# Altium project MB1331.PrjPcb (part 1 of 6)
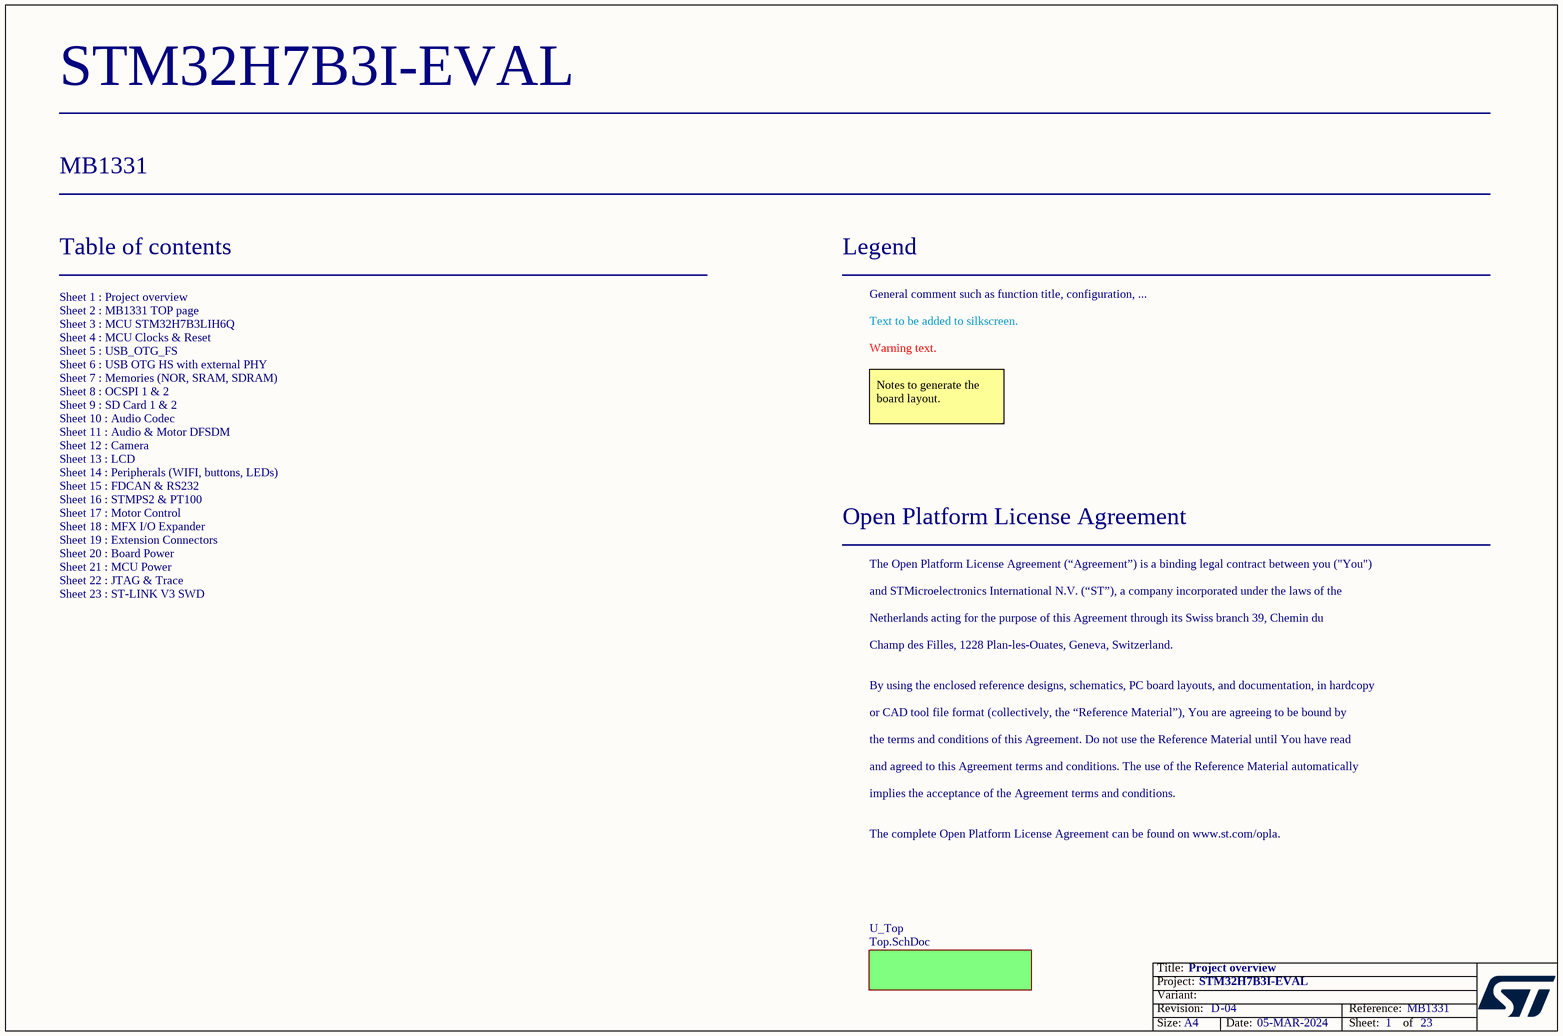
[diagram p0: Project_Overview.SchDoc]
Board_Assembly_Revision: 04; Board_Document_Date: 05-MAR-2024; Board_Name: STM32H7B3I-EVAL; Board_PCB_Revision: D; Board_Reference: MB1331
23 sheets, 916 parts. Net scope: flat (ports and power ports of the same name join across sheets).
Board file: MB1331.PcbDoc
Sheets:
  Project_Overview.SchDoc
    U_Top = Top.SchDoc
      U_SDcard = SDcard.SchDoc
      U_Camera = Camera.SchDoc
      U_MCU = MCU.SchDoc
      U_Audio_Codec = Audio_Codec.SchDoc
      U_DFSDM_Audio&Motor = DFSDM_Audio&Motor.SchDoc
      U_LCD = LCD.SchDoc
      U_JTAG&Trace = JTAG&Trace.SchDoc
      U_MCU_Clock&Reset = MCU_Clock&Reset.SchDoc
      U_Memory = Memory.SchDoc
      U_MFX = MFX.SchDoc
      U_MotorControl = MotorControl.SchDoc
      U_OCSPI = OCSPI.SchDoc
      U_Peripherals = Peripherals.SchDoc
      U_Power_Board = Power_Board.SchDoc
      U_STLink_V3E_SWD = STLink_V3E_SWD.SchDoc
      U_ExtensionConnector = ExtensionConnector.SchDoc
      U_USB_OTG_FS = USB_OTG_FS.SchDoc
      U_USB_OTG_HS_externalPHY = USB_OTG_HS_externalPHY.SchDoc
      U_FDCAN&RS232 = FDCAN&RS232.SchDoc
      U_STMPS2&PT100 = STMPS2&PT100.SchDoc
      U_Power_MCU = Power_MCU.SchDoc

## Sheet Project_Overview.SchDoc: Project overview
size A4; Date: Not used; ApprovedBy: Not used; CheckedBy: Not used; Author: Not used; CompanyName: STMicroelectronics; DrawnBy: Not used; Engineer: Not used; Organization: Not used; Address1: Not used; Address2: Not used; Address3: Not used; Address4: Not used; DocumentNumber: Not used; Revision: Not used; SheetNumber: 1; SheetTotal: 23

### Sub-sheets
U_Top = Top.SchDoc: no entries

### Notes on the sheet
- Table of contents
- Legend
- General comment such as function title, configuration, ...
- Text to be added to silkscreen.
- Warning text.
- Notes to generate the board layout.
- Open Platform License Agreement
- The Open Platform License Agreement (“Agreement”) is a binding legal contract between you ("You")
- Sheet 1 : Project overview
  Sheet 2 : MB1331 TOP page
  Sheet 3 : MCU STM32H7B3LIH6Q
  Sheet 4 : MCU Clocks & Reset
  Sheet 5 : USB_OTG_FS
  Sheet 6 : USB OTG HS with external PHY
  Sheet 7 : Memories (NOR, SRAM, SDRAM)
  Sheet 8 : OCSPI 1 & 2
  Sheet 9 : SD Card 1 & 2
  Sheet 10 : Audio Codec
  Sheet 11 : Audio & Motor DFSDM
  Sheet 12 : Camera
  Sheet 13 : LCD
  Sheet 14 : Peripherals (WIFI, buttons, LEDs)
  Sheet 15 : FDCAN & RS232
  Sheet 16 : STMPS2 & PT100
  Sheet 17 : Motor Control
  Sheet 18 : MFX I/O Expander
  Sheet 19 : Extension Connectors
  Sheet 20 : Board Power
  Sheet 21 : MCU Power
  Sheet 22 : JTAG & Trace
  Sheet 23 : ST-LINK V3 SWD
- and STMicroelectronics International N.V. (“ST”), a company incorporated under the laws of the
- Netherlands acting for the purpose of this Agreement through its Swiss branch 39, Chemin du
- Champ des Filles, 1228 Plan-les-Ouates, Geneva, Switzerland.
- By using the enclosed reference designs, schematics, PC board layouts, and documentation, in hardcopy
- or CAD tool file format (collectively, the “Reference Material”), You are agreeing to be bound by
- the terms and conditions of this Agreement. Do not use the Reference Material until You have read
- and agreed to this Agreement terms and conditions. The use of the Reference Material automatically
- implies the acceptance of the Agreement terms and conditions.
- The complete Open Platform License Agreement can be found on www.st.com/opla.

## Sheet Top.SchDoc: MB1331 TOP page
size A3; Date: Not used; ApprovedBy: Not used; CheckedBy: Not used; Author: Not used; CompanyName: STMicroelectronics; DrawnBy: Not used; Engineer: Not used; Organization: Not used; Address1: Not used; Address2: Not used; Address3: Not used; Address4: Not used; DocumentNumber: Not used; Revision: Not used; SheetNumber: 2; SheetTotal: 23
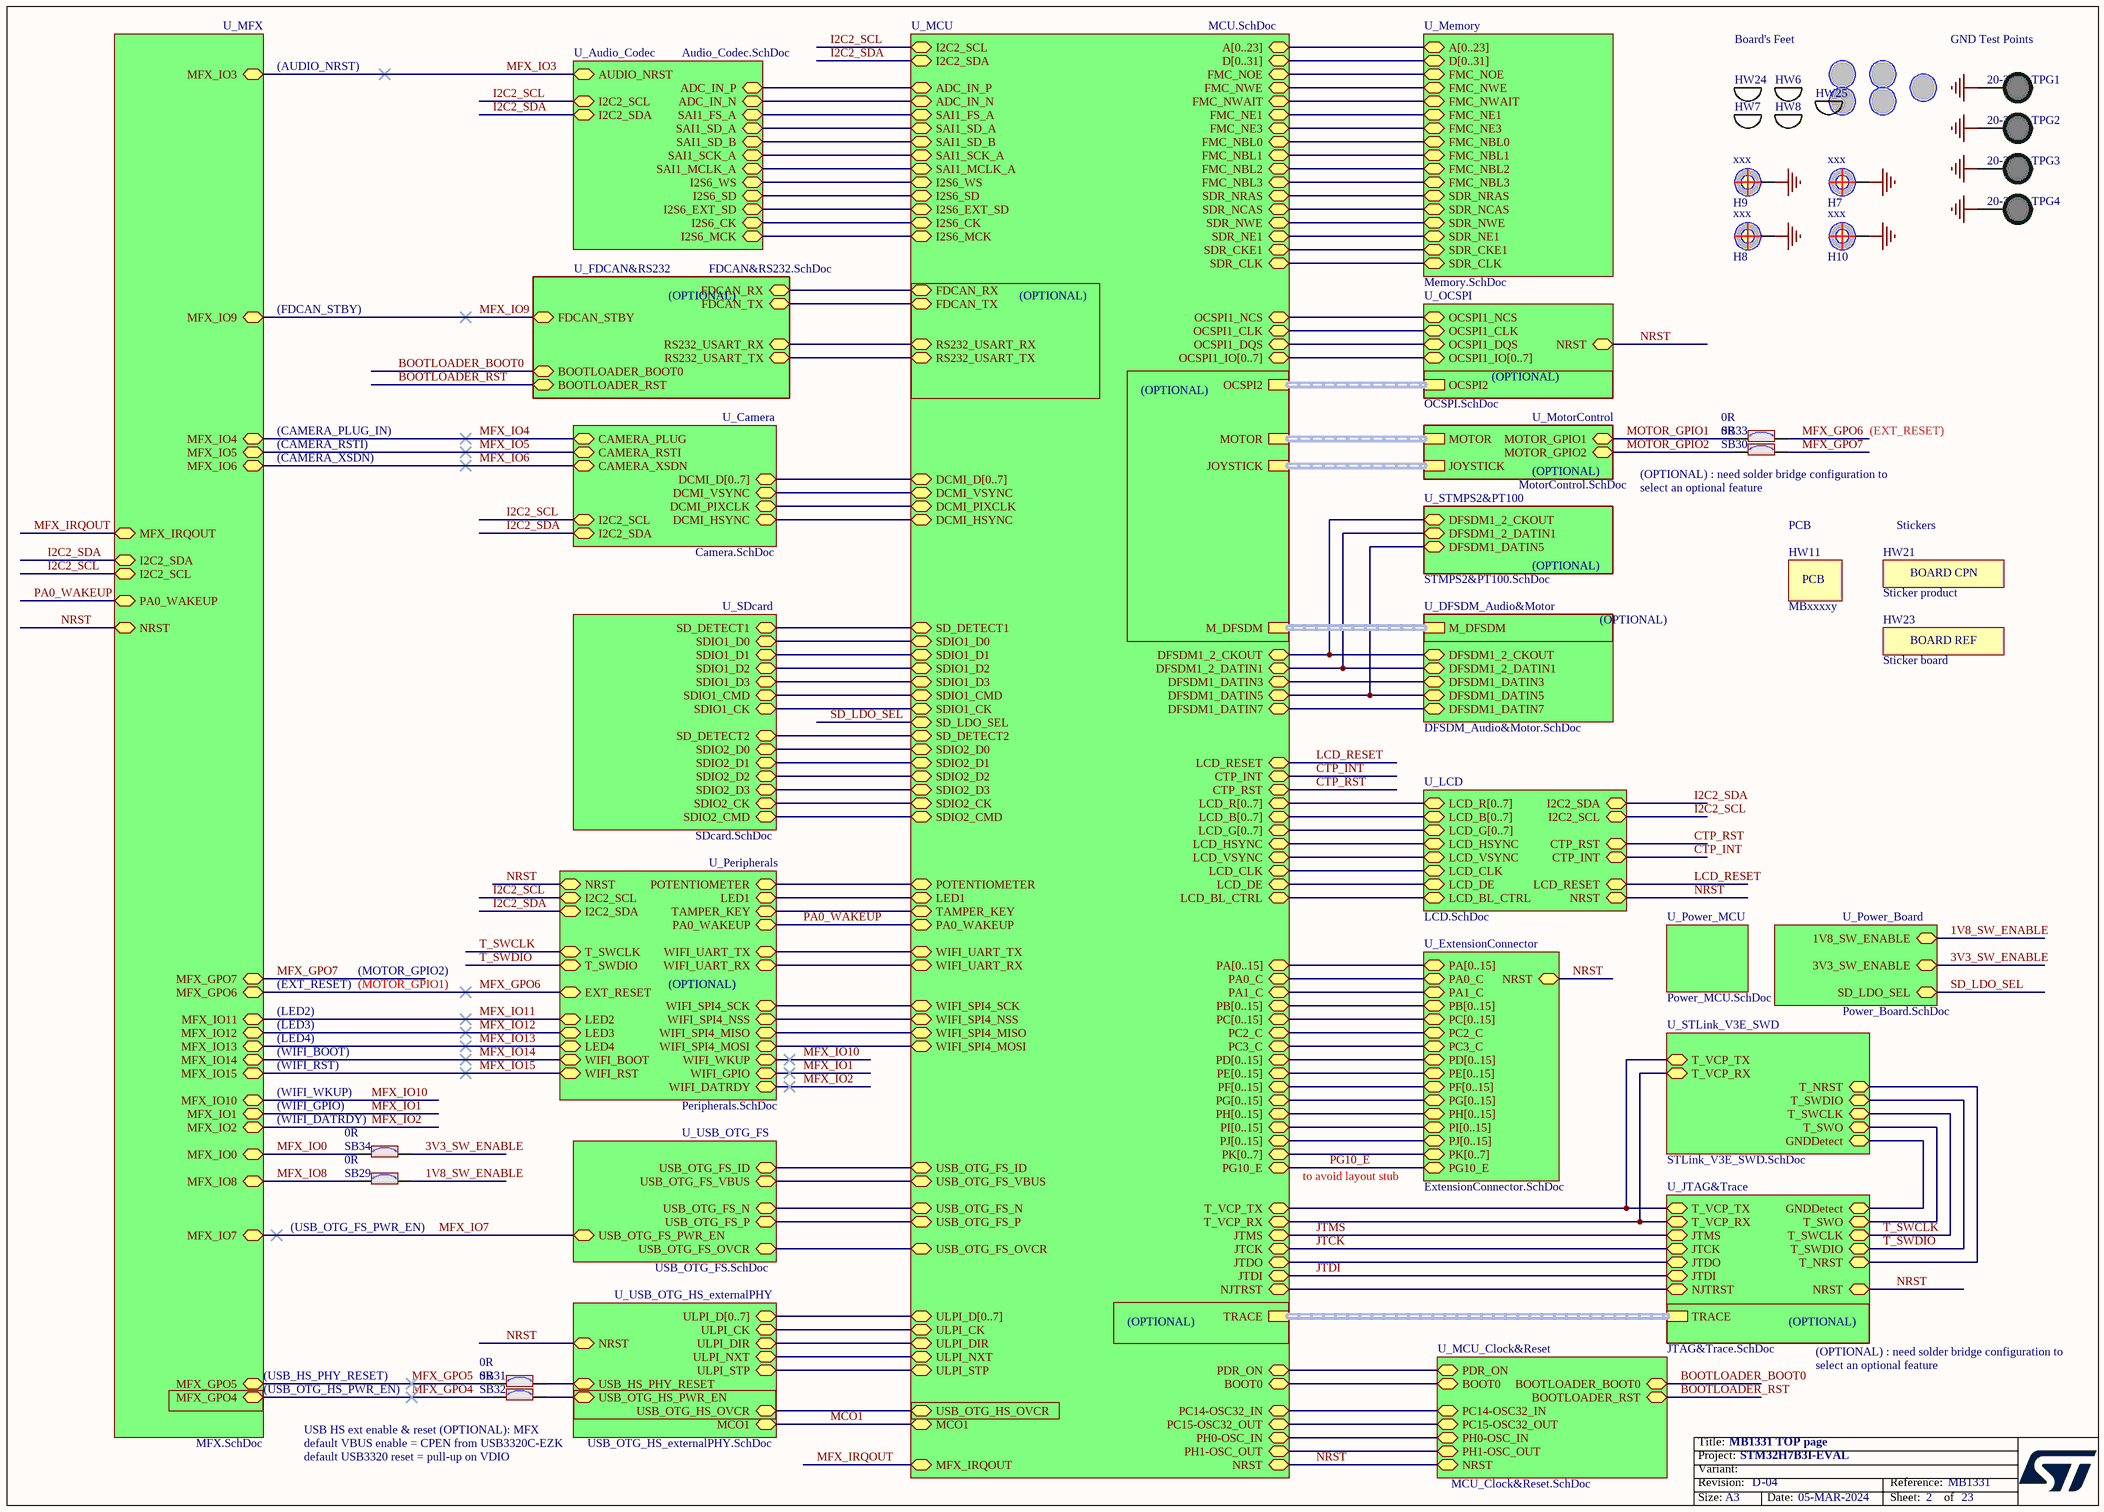
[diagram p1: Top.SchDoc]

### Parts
H7  value xxx  [PTH_M1261-3005-N_3P5X6_M3_H14]  (hidden comment: POSITION HOLE)  (no BOM)
H8  value xxx  [PTH_M1261-3005-N_3P5X6_M3_H14]  (hidden comment: POSITION HOLE)  (no BOM)
H9  value xxx  [PTH_M1261-3005-N_3P5X6_M3_H14]  (hidden comment: POSITION HOLE)  (no BOM)
H10  value xxx  [PTH_M1261-3005-N_3P5X6_M3_H14]  (hidden comment: POSITION HOLE)  (no BOM)
HW6  RUBBER_FOOT  (value not drawn)  (mechanical)
HW7  RUBBER_FOOT  (value not drawn)  (mechanical)
HW8  RUBBER_FOOT  (value not drawn)  (mechanical)
HW11  value MBxxxxy  (hidden comment: PCB)  (no BOM)
HW21  value Sticker product  [STICKER_25X9]  (hidden comment: STICKER_BOARD_CPN)  (no BOM)
HW23  value Sticker board  [STICKER_25X9]  (hidden comment: STICKER_BOARD_REF)  (no BOM)
HW24  RUBBER_FOOT  (value not drawn)  (mechanical)
HW25  RUBBER_FOOT  (value not drawn)  (mechanical)
SB29  value 0R  [SOLDER-BRIDGE_R0603-0R]  (hidden comment: SB_ON)
SB30  value 0R  [SOLDER-BRIDGE_R0603-0R]  (hidden comment: SB_ON)
SB31  value 0R  [SOLDER-BRIDGE_R0603-0R]  (hidden comment: SB_ON)
SB32  value 0R  [SOLDER-BRIDGE_R0603-0R]  (hidden comment: SB_ON)
SB33  value 0R  [SOLDER-BRIDGE_R0603-0R]  (hidden comment: SB_ON)
SB34  value 0R  [SOLDER-BRIDGE_R0603-0R]  (hidden comment: SB_ON)
TPG1  value 20-2137  [TP_PTH-1P02MM_TEST-TERMINAL_RS_101-2391_BLACK]  (hidden comment: Test_pin_conn_black)
TPG2  value 20-2137  [TP_PTH-1P02MM_TEST-TERMINAL_RS_101-2391_BLACK]  (hidden comment: Test_pin_conn_black)
TPG3  value 20-2137  [TP_PTH-1P02MM_TEST-TERMINAL_RS_101-2391_BLACK]  (hidden comment: Test_pin_conn_black)
TPG4  value 20-2137  [TP_PTH-1P02MM_TEST-TERMINAL_RS_101-2391_BLACK]  (hidden comment: Test_pin_conn_black)

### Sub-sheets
U_Audio_Codec = Audio_Codec.SchDoc: AUDIO_NRST (bidir), SAI1_SD_A (bidir), SAI1_SD_B (bidir), I2C2_SCL (bidir), I2C2_SDA (bidir), I2S6_WS (bidir), I2S6_EXT_SD (bidir), SAI1_FS_A (bidir), SAI1_SCK_A (bidir), SAI1_MCLK_A (bidir), ADC_IN_N (bidir), ADC_IN_P (bidir), I2S6_MCK (bidir), I2S6_CK (bidir), I2S6_SD (bidir)
U_Camera = Camera.SchDoc: CAMERA_RSTI (bidir), CAMERA_XSDN (bidir), DCMI_D[0..7] (bidir), CAMERA_PLUG (bidir), DCMI_HSYNC (bidir), DCMI_PIXCLK (bidir), DCMI_VSYNC (bidir), I2C2_SCL (bidir), I2C2_SDA (bidir)
U_DFSDM_Audio&Motor = DFSDM_Audio&Motor.SchDoc: DFSDM1_DATIN7 (bidir), DFSDM1_2_CKOUT (bidir), DFSDM1_2_DATIN1 (bidir), DFSDM1_DATIN3 (bidir), DFSDM1_DATIN5 (bidir), M_DFSDM (harness M_DFSDM)
U_ExtensionConnector = ExtensionConnector.SchDoc: PA[0..15] (bidir), PB[0..15] (bidir), PC[0..15] (bidir), PD[0..15] (bidir), PE[0..15] (bidir), PF[0..15] (bidir), PG[0..15] (bidir), PH[0..15] (bidir), PI[0..15] (bidir), PJ[0..15] (bidir), PK[0..7] (bidir), NRST (bidir), PA0_C (bidir), PA1_C (bidir), PC2_C (bidir), PC3_C (bidir), PG10_E (bidir)
U_FDCAN&RS232 = FDCAN&RS232.SchDoc: RS232_USART_TX (bidir), RS232_USART_RX (bidir), BOOTLOADER_BOOT0 (bidir), BOOTLOADER_RST (bidir), FDCAN_RX (bidir), FDCAN_TX (bidir), FDCAN_STBY (bidir)
U_JTAG&Trace = JTAG&Trace.SchDoc: JTMS (bidir), JTCK (bidir), JTDI (bidir), JTDO (bidir), NJTRST (bidir), NRST (bidir), TRACE (harness TRACE), T_VCP_TX (bidir), T_VCP_RX (bidir), GNDDetect (bidir), T_SWCLK (bidir), T_SWO (bidir), T_SWDIO (bidir), T_NRST (bidir)
U_LCD = LCD.SchDoc: LCD_R[0..7] (bidir), I2C2_SDA (bidir), I2C2_SCL (bidir), LCD_B[0..7] (bidir), LCD_G[0..7] (bidir), NRST (bidir), LCD_HSYNC (bidir), LCD_VSYNC (bidir), LCD_CLK (bidir), LCD_DE (bidir), CTP_INT (bidir), LCD_BL_CTRL (bidir), CTP_RST (bidir), LCD_RESET (bidir)
U_MCU = MCU.SchDoc: OCSPI1_NCS (bidir), SDR_CLK (bidir), FMC_NE3 (bidir), SDR_NCAS (bidir), SDR_NWE (bidir), SDR_NE1 (bidir), SDR_CKE1 (bidir), PH0-OSC_IN (bidir), NRST (bidir), BOOT0 (bidir), PDR_ON (bidir), FMC_NBL2 (bidir), FMC_NBL3 (bidir), LCD_HSYNC (bidir), LCD_VSYNC (bidir), LCD_CLK (bidir), PA0_WAKEUP (bidir), MCO1 (bidir), USB_OTG_FS_VBUS (bidir), USB_OTG_FS_ID (bidir), USB_OTG_FS_N (bidir), USB_OTG_FS_P (bidir), OCSPI1_CLK (bidir), T_VCP_TX (bidir), T_VCP_RX (bidir), OCSPI1_DQS (bidir), SDIO1_D0 (bidir), SDIO1_D1 (bidir), SDIO1_D2 (bidir), SDIO1_D3 (bidir), SDIO1_CK (bidir), TAMPER_KEY (bidir), PC14-OSC32_IN (bidir), PC15-OSC32_OUT (bidir), SDIO1_CMD (bidir), FMC_NOE (bidir), FMC_NWE (bidir), FMC_NWAIT (bidir), FMC_NE1 (bidir), FMC_NBL0 (bidir), FMC_NBL1 (bidir), SDR_NRAS (bidir), DFSDM1_DATIN7 (bidir), DFSDM1_2_CKOUT (bidir), DCMI_HSYNC (bidir), DCMI_PIXCLK (bidir), DCMI_VSYNC (bidir), FDCAN_RX (bidir), FDCAN_TX (bidir), PA[0..15] (bidir), PB[0..15] (bidir), PC[0..15] (bidir), PD[0..15] (bidir), PE[0..15] (bidir), PF[0..15] (bidir), PG[0..15] (bidir), PH[0..15] (bidir), PI[0..15] (bidir), PJ[0..15] (bidir), PK[0..7] (bidir), LCD_G[0..7] (bidir), LCD_B[0..7] (bidir), D[0..31] (bidir), A[0..23] (bidir), ULPI_D[0..7] (bidir), LCD_R[0..7] (bidir), LCD_DE (bidir), DFSDM1_2_DATIN1 (bidir), I2C2_SCL (bidir), I2C2_SDA (bidir), DCMI_D[0..7] (bidir), POTENTIOMETER (bidir), ULPI_NXT (bidir), ULPI_DIR (bidir), ULPI_STP (bidir), ULPI_CK (bidir), CTP_INT (bidir), CTP_RST (bidir), LCD_BL_CTRL (bidir), OCSPI1_IO[0..7] (bidir), PA0_C (bidir), PA1_C (bidir), PC2_C (bidir), PC3_C (bidir), JTMS (bidir), JTCK (bidir), JTDI (bidir), JTDO (bidir), NJTRST (bidir), DFSDM1_DATIN3 (bidir), DFSDM1_DATIN5 (bidir), LCD_RESET (bidir), MFX_IRQOUT (bidir), RS232_USART_TX (bidir), RS232_USART_RX (bidir), SDIO2_CK (bidir), SDIO2_D2 (bidir), SDIO2_D1 (bidir), SDIO2_D3 (bidir), SDIO2_D0 (bidir), SDIO2_CMD (bidir), JOYSTICK (harness JOYSTICK), MOTOR (harness MOTOR), OCSPI2 (harness OCSPI2), TRACE (harness TRACE), M_DFSDM (harness M_DFSDM), PH1-OSC_OUT (bidir), WIFI_SPI4_SCK (bidir), WIFI_SPI4_NSS (bidir), WIFI_SPI4_MISO (bidir), WIFI_SPI4_MOSI (bidir), USB_OTG_FS_OVCR (bidir), LED1 (bidir), ADC_IN_N (bidir), ADC_IN_P (bidir), USB_OTG_HS_OVCR (bidir), SD_DETECT1 (bidir), SD_DETECT2 (bidir), SD_LDO_SEL (bidir), SAI1_SD_A (bidir), SAI1_SD_B (bidir), I2S6_WS (bidir), I2S6_EXT_SD (bidir), SAI1_FS_A (bidir), SAI1_SCK_A (bidir), SAI1_MCLK_A (bidir), I2S6_MCK (bidir), I2S6_CK (bidir), I2S6_SD (bidir), PG10_E (bidir), WIFI_UART_TX (bidir), WIFI_UART_RX (bidir)
U_MCU_Clock&Reset = MCU_Clock&Reset.SchDoc: BOOTLOADER_BOOT0 (bidir), BOOTLOADER_RST (bidir), NRST (bidir), BOOT0 (bidir), PDR_ON (bidir), PH0-OSC_IN (bidir), PC14-OSC32_IN (bidir), PC15-OSC32_OUT (bidir), PH1-OSC_OUT (bidir)
U_Memory = Memory.SchDoc: FMC_NE1 (bidir), FMC_NWE (bidir), FMC_NOE (bidir), FMC_NWAIT (bidir), FMC_NBL0 (bidir), FMC_NBL1 (bidir), D[0..31] (bidir), A[0..23] (bidir), SDR_NCAS (bidir), SDR_NWE (bidir), SDR_NRAS (bidir), SDR_NE1 (bidir), SDR_CKE1 (bidir), SDR_CLK (bidir), FMC_NBL3 (bidir), FMC_NBL2 (bidir), FMC_NE3 (bidir)
U_MFX = MFX.SchDoc: MFX_IRQOUT (bidir), I2C2_SDA (bidir), I2C2_SCL (bidir), PA0_WAKEUP (bidir), NRST (bidir), MFX_IO9 (bidir), MFX_IO4 (bidir), MFX_IO5 (bidir), MFX_IO6 (bidir), MFX_IO8 (bidir), MFX_IO3 (bidir), MFX_IO7 (bidir), MFX_IO14 (bidir), MFX_IO15 (bidir), MFX_IO12 (bidir), MFX_IO11 (bidir), MFX_IO13 (bidir), MFX_GPO5 (bidir), MFX_GPO4 (bidir), MFX_IO0 (bidir), MFX_GPO6 (bidir), MFX_GPO7 (bidir), MFX_IO1 (bidir), MFX_IO2 (bidir), MFX_IO10 (bidir)
U_MotorControl = MotorControl.SchDoc: MOTOR (harness MOTOR), JOYSTICK (harness JOYSTICK), MOTOR_GPIO1 (bidir), MOTOR_GPIO2 (bidir)
U_OCSPI = OCSPI.SchDoc: NRST (bidir), OCSPI1_NCS (bidir), OCSPI1_DQS (bidir), OCSPI1_CLK (bidir), OCSPI1_IO[0..7] (bidir), OCSPI2 (harness OCSPI2)
U_Peripherals = Peripherals.SchDoc: POTENTIOMETER (bidir), LED1 (bidir), LED2 (bidir), LED3 (bidir), LED4 (bidir), WIFI_UART_RX (bidir), WIFI_UART_TX (bidir), WIFI_RST (bidir), EXT_RESET (bidir), TAMPER_KEY (bidir), NRST (bidir), PA0_WAKEUP (bidir), I2C2_SCL (bidir), I2C2_SDA (bidir), WIFI_BOOT (bidir), WIFI_SPI4_SCK (bidir), WIFI_SPI4_NSS (bidir), WIFI_SPI4_MISO (bidir), WIFI_SPI4_MOSI (bidir), T_SWCLK (bidir), T_SWDIO (bidir), WIFI_WKUP (bidir), WIFI_GPIO (bidir), WIFI_DATRDY (bidir)
U_Power_Board = Power_Board.SchDoc: 1V8_SW_ENABLE (bidir), 3V3_SW_ENABLE (bidir), SD_LDO_SEL (bidir)
U_Power_MCU = Power_MCU.SchDoc: no entries
U_SDcard = SDcard.SchDoc: SDIO1_D0 (bidir), SDIO1_D1 (bidir), SDIO1_D2 (bidir), SDIO1_D3 (bidir), SDIO1_CMD (bidir), SD_DETECT2 (bidir), SDIO1_CK (bidir), SDIO2_CK (bidir), SDIO2_D2 (bidir), SDIO2_D1 (bidir), SDIO2_D3 (bidir), SDIO2_D0 (bidir), SDIO2_CMD (bidir), SD_DETECT1 (bidir)
U_STLink_V3E_SWD = STLink_V3E_SWD.SchDoc: T_SWCLK (bidir), T_SWO (bidir), T_SWDIO (bidir), T_VCP_TX (bidir), T_VCP_RX (bidir), GNDDetect (bidir), T_NRST (bidir)
U_STMPS2&PT100 = STMPS2&PT100.SchDoc: DFSDM1_2_CKOUT (bidir), DFSDM1_2_DATIN1 (bidir), DFSDM1_DATIN5 (bidir)
U_USB_OTG_FS = USB_OTG_FS.SchDoc: USB_OTG_FS_VBUS (bidir), USB_OTG_FS_N (bidir), USB_OTG_FS_P (bidir), USB_OTG_FS_ID (bidir), USB_OTG_FS_PWR_EN (bidir), USB_OTG_FS_OVCR (bidir)
U_USB_OTG_HS_externalPHY = USB_OTG_HS_externalPHY.SchDoc: ULPI_D[0..7] (bidir), ULPI_CK (bidir), ULPI_DIR (bidir), ULPI_NXT (bidir), ULPI_STP (bidir), USB_HS_PHY_RESET (bidir), NRST (bidir), USB_OTG_HS_PWR_EN (bidir), USB_OTG_HS_OVCR (bidir), MCO1 (bidir)

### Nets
GND: H7.1 H8.1 H9.1 H10.1 TPG1.1 TPG2.1 TPG3.1 TPG4.1
1V8_SW_ENABLE: SB29.1 ; sheet U_Power_Board/1V8_SW_ENABLE
3V3_SW_ENABLE: SB34.1 ; sheet U_Power_Board/3V3_SW_ENABLE
BOOTLOADER_BOOT0: sheet U_MCU_Clock&Reset/BOOTLOADER_BOOT0, sheet U_FDCAN&RS232/BOOTLOADER_BOOT0
BOOTLOADER_RST: sheet U_MCU_Clock&Reset/BOOTLOADER_RST, sheet U_FDCAN&RS232/BOOTLOADER_RST
CTP_INT: sheet U_MCU/CTP_INT, sheet U_LCD/CTP_INT
CTP_RST: sheet U_MCU/CTP_RST, sheet U_LCD/CTP_RST
I2C2_SCL: sheet U_Camera/I2C2_SCL, sheet U_MCU/I2C2_SCL, sheet U_Audio_Codec/I2C2_SCL, sheet U_LCD/I2C2_SCL, sheet U_MFX/I2C2_SCL, sheet U_Peripherals/I2C2_SCL
I2C2_SDA: sheet U_Camera/I2C2_SDA, sheet U_MCU/I2C2_SDA, sheet U_Audio_Codec/I2C2_SDA, sheet U_LCD/I2C2_SDA, sheet U_MFX/I2C2_SDA, sheet U_Peripherals/I2C2_SDA
JTCK: sheet U_MCU/JTCK, sheet U_JTAG&Trace/JTCK
JTDI: sheet U_MCU/JTDI, sheet U_JTAG&Trace/JTDI
JTMS: sheet U_MCU/JTMS, sheet U_JTAG&Trace/JTMS
LCD_RESET: sheet U_MCU/LCD_RESET, sheet U_LCD/LCD_RESET
MCO1: sheet U_MCU/MCO1, sheet U_USB_OTG_HS_externalPHY/MCO1
MFX_GPO4: SB32.2 ; sheet U_MFX/MFX_GPO4
MFX_GPO5: SB31.2 ; sheet U_MFX/MFX_GPO5
MFX_GPO6: SB33.1 ; sheet U_MFX/MFX_GPO6, sheet U_Peripherals/EXT_RESET
MFX_GPO7: SB30.1 ; sheet U_MFX/MFX_GPO7
MFX_IO0: SB34.2 ; sheet U_MFX/MFX_IO0
MFX_IO1: sheet U_MFX/MFX_IO1, sheet U_Peripherals/WIFI_GPIO
MFX_IO2: sheet U_MFX/MFX_IO2, sheet U_Peripherals/WIFI_DATRDY
MFX_IO3: sheet U_Audio_Codec/AUDIO_NRST, sheet U_MFX/MFX_IO3
MFX_IO4: sheet U_Camera/CAMERA_PLUG, sheet U_MFX/MFX_IO4
MFX_IO5: sheet U_Camera/CAMERA_RSTI, sheet U_MFX/MFX_IO5
MFX_IO6: sheet U_Camera/CAMERA_XSDN, sheet U_MFX/MFX_IO6
MFX_IO7: sheet U_MFX/MFX_IO7, sheet U_USB_OTG_FS/USB_OTG_FS_PWR_EN
MFX_IO8: SB29.2 ; sheet U_MFX/MFX_IO8
MFX_IO9: sheet U_MFX/MFX_IO9, sheet U_FDCAN&RS232/FDCAN_STBY
MFX_IO10: sheet U_MFX/MFX_IO10, sheet U_Peripherals/WIFI_WKUP
MFX_IO11: sheet U_MFX/MFX_IO11, sheet U_Peripherals/LED2
MFX_IO12: sheet U_MFX/MFX_IO12, sheet U_Peripherals/LED3
MFX_IO13: sheet U_MFX/MFX_IO13, sheet U_Peripherals/LED4
MFX_IO14: sheet U_MFX/MFX_IO14, sheet U_Peripherals/WIFI_BOOT
MFX_IO15: sheet U_MFX/MFX_IO15, sheet U_Peripherals/WIFI_RST
MFX_IRQOUT: sheet U_MCU/MFX_IRQOUT, sheet U_MFX/MFX_IRQOUT
MOTOR_GPIO1: SB33.2 ; sheet U_MotorControl/MOTOR_GPIO1
MOTOR_GPIO2: SB30.2 ; sheet U_MotorControl/MOTOR_GPIO2
NRST: sheet U_MCU/NRST, sheet U_LCD/NRST, sheet U_JTAG&Trace/NRST, sheet U_MCU_Clock&Reset/NRST, sheet U_MFX/NRST, sheet U_OCSPI/NRST, sheet U_Peripherals/NRST, sheet U_ExtensionConnector/NRST, sheet U_USB_OTG_HS_externalPHY/NRST
PA0_WAKEUP: sheet U_MCU/PA0_WAKEUP, sheet U_MFX/PA0_WAKEUP, sheet U_Peripherals/PA0_WAKEUP
PG10_E: sheet U_MCU/PG10_E, sheet U_ExtensionConnector/PG10_E
SD_LDO_SEL: sheet U_MCU/SD_LDO_SEL, sheet U_Power_Board/SD_LDO_SEL
T_SWCLK: sheet U_JTAG&Trace/T_SWCLK, sheet U_Peripherals/T_SWCLK, sheet U_STLink_V3E_SWD/T_SWCLK
T_SWDIO: sheet U_JTAG&Trace/T_SWDIO, sheet U_Peripherals/T_SWDIO, sheet U_STLink_V3E_SWD/T_SWDIO
NetSB31_1: SB31.1 ; sheet U_USB_OTG_HS_externalPHY/USB_HS_PHY_RESET
NetSB32_1: SB32.1 ; sheet U_USB_OTG_HS_externalPHY/USB_OTG_HS_PWR_EN
(unnamed): sheet U_SDcard/SDIO1_D0, sheet U_MCU/SDIO1_D0
(unnamed): sheet U_SDcard/SDIO1_D1, sheet U_MCU/SDIO1_D1  [a separate net that carries the same name]
(unnamed): sheet U_SDcard/SDIO1_D2, sheet U_MCU/SDIO1_D2  [a separate net that carries the same name]
(unnamed): sheet U_SDcard/SDIO1_D3, sheet U_MCU/SDIO1_D3  [a separate net that carries the same name]
(unnamed): sheet U_SDcard/SDIO1_CMD, sheet U_MCU/SDIO1_CMD  [a separate net that carries the same name]
(unnamed): sheet U_SDcard/SD_DETECT2, sheet U_MCU/SD_DETECT2  [a separate net that carries the same name]
(unnamed): sheet U_SDcard/SDIO1_CK, sheet U_MCU/SDIO1_CK  [a separate net that carries the same name]
(unnamed): sheet U_SDcard/SDIO2_CK, sheet U_MCU/SDIO2_CK  [a separate net that carries the same name]
(unnamed): sheet U_SDcard/SDIO2_D2, sheet U_MCU/SDIO2_D2  [a separate net that carries the same name]
(unnamed): sheet U_SDcard/SDIO2_D1, sheet U_MCU/SDIO2_D1  [a separate net that carries the same name]
(unnamed): sheet U_SDcard/SDIO2_D3, sheet U_MCU/SDIO2_D3  [a separate net that carries the same name]
(unnamed): sheet U_SDcard/SDIO2_D0, sheet U_MCU/SDIO2_D0  [a separate net that carries the same name]
(unnamed): sheet U_SDcard/SDIO2_CMD, sheet U_MCU/SDIO2_CMD  [a separate net that carries the same name]
(unnamed): sheet U_SDcard/SD_DETECT1, sheet U_MCU/SD_DETECT1  [a separate net that carries the same name]
(unnamed): sheet U_Camera/DCMI_HSYNC, sheet U_MCU/DCMI_HSYNC  [a separate net that carries the same name]
(unnamed): sheet U_Camera/DCMI_PIXCLK, sheet U_MCU/DCMI_PIXCLK  [a separate net that carries the same name]
(unnamed): sheet U_Camera/DCMI_VSYNC, sheet U_MCU/DCMI_VSYNC  [a separate net that carries the same name]
(unnamed): sheet U_MCU/OCSPI1_NCS, sheet U_OCSPI/OCSPI1_NCS  [a separate net that carries the same name]
(unnamed): sheet U_MCU/SDR_CLK, sheet U_Memory/SDR_CLK  [a separate net that carries the same name]
(unnamed): sheet U_MCU/FMC_NE3, sheet U_Memory/FMC_NE3  [a separate net that carries the same name]
(unnamed): sheet U_MCU/SDR_NCAS, sheet U_Memory/SDR_NCAS  [a separate net that carries the same name]
(unnamed): sheet U_MCU/SDR_NWE, sheet U_Memory/SDR_NWE  [a separate net that carries the same name]
(unnamed): sheet U_MCU/SDR_NE1, sheet U_Memory/SDR_NE1  [a separate net that carries the same name]
(unnamed): sheet U_MCU/SDR_CKE1, sheet U_Memory/SDR_CKE1  [a separate net that carries the same name]
(unnamed): sheet U_MCU/PH0-OSC_IN, sheet U_MCU_Clock&Reset/PH0-OSC_IN  [a separate net that carries the same name]
(unnamed): sheet U_MCU/BOOT0, sheet U_MCU_Clock&Reset/BOOT0  [a separate net that carries the same name]
(unnamed): sheet U_MCU/PDR_ON, sheet U_MCU_Clock&Reset/PDR_ON  [a separate net that carries the same name]
(unnamed): sheet U_MCU/FMC_NBL2, sheet U_Memory/FMC_NBL2  [a separate net that carries the same name]
(unnamed): sheet U_MCU/FMC_NBL3, sheet U_Memory/FMC_NBL3  [a separate net that carries the same name]
(unnamed): sheet U_MCU/LCD_HSYNC, sheet U_LCD/LCD_HSYNC  [a separate net that carries the same name]
(unnamed): sheet U_MCU/LCD_VSYNC, sheet U_LCD/LCD_VSYNC  [a separate net that carries the same name]
(unnamed): sheet U_MCU/LCD_CLK, sheet U_LCD/LCD_CLK  [a separate net that carries the same name]
(unnamed): sheet U_MCU/USB_OTG_FS_VBUS, sheet U_USB_OTG_FS/USB_OTG_FS_VBUS  [a separate net that carries the same name]
(unnamed): sheet U_MCU/USB_OTG_FS_ID, sheet U_USB_OTG_FS/USB_OTG_FS_ID  [a separate net that carries the same name]
(unnamed): sheet U_MCU/USB_OTG_FS_N, sheet U_USB_OTG_FS/USB_OTG_FS_N  [a separate net that carries the same name]
(unnamed): sheet U_MCU/USB_OTG_FS_P, sheet U_USB_OTG_FS/USB_OTG_FS_P  [a separate net that carries the same name]
(unnamed): sheet U_MCU/OCSPI1_CLK, sheet U_OCSPI/OCSPI1_CLK  [a separate net that carries the same name]
(unnamed): sheet U_MCU/T_VCP_TX, sheet U_JTAG&Trace/T_VCP_TX, sheet U_STLink_V3E_SWD/T_VCP_TX  [a separate net that carries the same name]
(unnamed): sheet U_MCU/T_VCP_RX, sheet U_JTAG&Trace/T_VCP_RX, sheet U_STLink_V3E_SWD/T_VCP_RX  [a separate net that carries the same name]
(unnamed): sheet U_MCU/OCSPI1_DQS, sheet U_OCSPI/OCSPI1_DQS  [a separate net that carries the same name]
(unnamed): sheet U_MCU/TAMPER_KEY, sheet U_Peripherals/TAMPER_KEY  [a separate net that carries the same name]
(unnamed): sheet U_MCU/PC14-OSC32_IN, sheet U_MCU_Clock&Reset/PC14-OSC32_IN  [a separate net that carries the same name]
(unnamed): sheet U_MCU/PC15-OSC32_OUT, sheet U_MCU_Clock&Reset/PC15-OSC32_OUT  [a separate net that carries the same name]
(unnamed): sheet U_MCU/FMC_NOE, sheet U_Memory/FMC_NOE  [a separate net that carries the same name]
(unnamed): sheet U_MCU/FMC_NWE, sheet U_Memory/FMC_NWE  [a separate net that carries the same name]
(unnamed): sheet U_MCU/FMC_NWAIT, sheet U_Memory/FMC_NWAIT  [a separate net that carries the same name]
(unnamed): sheet U_MCU/FMC_NE1, sheet U_Memory/FMC_NE1  [a separate net that carries the same name]
(unnamed): sheet U_MCU/FMC_NBL0, sheet U_Memory/FMC_NBL0  [a separate net that carries the same name]
(unnamed): sheet U_MCU/FMC_NBL1, sheet U_Memory/FMC_NBL1  [a separate net that carries the same name]
(unnamed): sheet U_MCU/SDR_NRAS, sheet U_Memory/SDR_NRAS  [a separate net that carries the same name]
(unnamed): sheet U_MCU/DFSDM1_DATIN7, sheet U_DFSDM_Audio&Motor/DFSDM1_DATIN7  [a separate net that carries the same name]
(unnamed): sheet U_MCU/DFSDM1_2_CKOUT, sheet U_DFSDM_Audio&Motor/DFSDM1_2_CKOUT, sheet U_STMPS2&PT100/DFSDM1_2_CKOUT  [a separate net that carries the same name]
(unnamed): sheet U_MCU/FDCAN_RX, sheet U_FDCAN&RS232/FDCAN_RX  [a separate net that carries the same name]
(unnamed): sheet U_MCU/FDCAN_TX, sheet U_FDCAN&RS232/FDCAN_TX  [a separate net that carries the same name]
(unnamed): sheet U_MCU/LCD_DE, sheet U_LCD/LCD_DE  [a separate net that carries the same name]
(unnamed): sheet U_MCU/DFSDM1_2_DATIN1, sheet U_DFSDM_Audio&Motor/DFSDM1_2_DATIN1, sheet U_STMPS2&PT100/DFSDM1_2_DATIN1  [a separate net that carries the same name]
(unnamed): sheet U_MCU/POTENTIOMETER, sheet U_Peripherals/POTENTIOMETER  [a separate net that carries the same name]
(unnamed): sheet U_MCU/ULPI_NXT, sheet U_USB_OTG_HS_externalPHY/ULPI_NXT  [a separate net that carries the same name]
(unnamed): sheet U_MCU/ULPI_DIR, sheet U_USB_OTG_HS_externalPHY/ULPI_DIR  [a separate net that carries the same name]
(unnamed): sheet U_MCU/ULPI_STP, sheet U_USB_OTG_HS_externalPHY/ULPI_STP  [a separate net that carries the same name]
(unnamed): sheet U_MCU/ULPI_CK, sheet U_USB_OTG_HS_externalPHY/ULPI_CK  [a separate net that carries the same name]
(unnamed): sheet U_MCU/LCD_BL_CTRL, sheet U_LCD/LCD_BL_CTRL  [a separate net that carries the same name]
(unnamed): sheet U_MCU/PA0_C, sheet U_ExtensionConnector/PA0_C  [a separate net that carries the same name]
(unnamed): sheet U_MCU/PA1_C, sheet U_ExtensionConnector/PA1_C  [a separate net that carries the same name]
(unnamed): sheet U_MCU/PC2_C, sheet U_ExtensionConnector/PC2_C  [a separate net that carries the same name]
(unnamed): sheet U_MCU/PC3_C, sheet U_ExtensionConnector/PC3_C  [a separate net that carries the same name]
(unnamed): sheet U_MCU/JTDO, sheet U_JTAG&Trace/JTDO  [a separate net that carries the same name]
(unnamed): sheet U_MCU/NJTRST, sheet U_JTAG&Trace/NJTRST  [a separate net that carries the same name]
(unnamed): sheet U_MCU/DFSDM1_DATIN3, sheet U_DFSDM_Audio&Motor/DFSDM1_DATIN3  [a separate net that carries the same name]
(unnamed): sheet U_MCU/DFSDM1_DATIN5, sheet U_DFSDM_Audio&Motor/DFSDM1_DATIN5, sheet U_STMPS2&PT100/DFSDM1_DATIN5  [a separate net that carries the same name]
(unnamed): sheet U_MCU/RS232_USART_TX, sheet U_FDCAN&RS232/RS232_USART_TX  [a separate net that carries the same name]
(unnamed): sheet U_MCU/RS232_USART_RX, sheet U_FDCAN&RS232/RS232_USART_RX  [a separate net that carries the same name]
(unnamed): sheet U_MCU/PH1-OSC_OUT, sheet U_MCU_Clock&Reset/PH1-OSC_OUT  [a separate net that carries the same name]
(unnamed): sheet U_MCU/WIFI_SPI4_SCK, sheet U_Peripherals/WIFI_SPI4_SCK  [a separate net that carries the same name]
(unnamed): sheet U_MCU/WIFI_SPI4_NSS, sheet U_Peripherals/WIFI_SPI4_NSS  [a separate net that carries the same name]
(unnamed): sheet U_MCU/WIFI_SPI4_MISO, sheet U_Peripherals/WIFI_SPI4_MISO  [a separate net that carries the same name]
(unnamed): sheet U_MCU/WIFI_SPI4_MOSI, sheet U_Peripherals/WIFI_SPI4_MOSI  [a separate net that carries the same name]
(unnamed): sheet U_MCU/USB_OTG_FS_OVCR, sheet U_USB_OTG_FS/USB_OTG_FS_OVCR  [a separate net that carries the same name]
(unnamed): sheet U_MCU/LED1, sheet U_Peripherals/LED1  [a separate net that carries the same name]
(unnamed): sheet U_MCU/ADC_IN_N, sheet U_Audio_Codec/ADC_IN_N  [a separate net that carries the same name]
(unnamed): sheet U_MCU/ADC_IN_P, sheet U_Audio_Codec/ADC_IN_P  [a separate net that carries the same name]
(unnamed): sheet U_MCU/USB_OTG_HS_OVCR, sheet U_USB_OTG_HS_externalPHY/USB_OTG_HS_OVCR  [a separate net that carries the same name]
(unnamed): sheet U_MCU/SAI1_SD_A, sheet U_Audio_Codec/SAI1_SD_A  [a separate net that carries the same name]
(unnamed): sheet U_MCU/SAI1_SD_B, sheet U_Audio_Codec/SAI1_SD_B  [a separate net that carries the same name]
(unnamed): sheet U_MCU/I2S6_WS, sheet U_Audio_Codec/I2S6_WS  [a separate net that carries the same name]
(unnamed): sheet U_MCU/I2S6_EXT_SD, sheet U_Audio_Codec/I2S6_EXT_SD  [a separate net that carries the same name]
(unnamed): sheet U_MCU/SAI1_FS_A, sheet U_Audio_Codec/SAI1_FS_A  [a separate net that carries the same name]
(unnamed): sheet U_MCU/SAI1_SCK_A, sheet U_Audio_Codec/SAI1_SCK_A  [a separate net that carries the same name]
(unnamed): sheet U_MCU/SAI1_MCLK_A, sheet U_Audio_Codec/SAI1_MCLK_A  [a separate net that carries the same name]
(unnamed): sheet U_MCU/I2S6_MCK, sheet U_Audio_Codec/I2S6_MCK  [a separate net that carries the same name]
(unnamed): sheet U_MCU/I2S6_CK, sheet U_Audio_Codec/I2S6_CK  [a separate net that carries the same name]
(unnamed): sheet U_MCU/I2S6_SD, sheet U_Audio_Codec/I2S6_SD  [a separate net that carries the same name]
(unnamed): sheet U_MCU/WIFI_UART_TX, sheet U_Peripherals/WIFI_UART_TX  [a separate net that carries the same name]
(unnamed): sheet U_MCU/WIFI_UART_RX, sheet U_Peripherals/WIFI_UART_RX  [a separate net that carries the same name]
(unnamed): sheet U_JTAG&Trace/GNDDetect, sheet U_STLink_V3E_SWD/GNDDetect  [a separate net that carries the same name]
(unnamed): sheet U_JTAG&Trace/T_SWO, sheet U_STLink_V3E_SWD/T_SWO  [a separate net that carries the same name]
(unnamed): sheet U_JTAG&Trace/T_NRST, sheet U_STLink_V3E_SWD/T_NRST  [a separate net that carries the same name]

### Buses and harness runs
bus sheet U_Camera/DCMI_D[0..7] = sheet U_MCU/DCMI_D[0..7]
bus sheet U_ExtensionConnector/PA[0..15] = sheet U_MCU/PA[0..15]
bus sheet U_ExtensionConnector/PB[0..15] = sheet U_MCU/PB[0..15]
bus sheet U_ExtensionConnector/PC[0..15] = sheet U_MCU/PC[0..15]
bus sheet U_ExtensionConnector/PD[0..15] = sheet U_MCU/PD[0..15]
bus sheet U_ExtensionConnector/PE[0..15] = sheet U_MCU/PE[0..15]
bus sheet U_ExtensionConnector/PF[0..15] = sheet U_MCU/PF[0..15]
bus sheet U_ExtensionConnector/PG[0..15] = sheet U_MCU/PG[0..15]
bus sheet U_ExtensionConnector/PH[0..15] = sheet U_MCU/PH[0..15]
bus sheet U_ExtensionConnector/PI[0..15] = sheet U_MCU/PI[0..15]
bus sheet U_ExtensionConnector/PJ[0..15] = sheet U_MCU/PJ[0..15]
bus sheet U_ExtensionConnector/PK[0..7] = sheet U_MCU/PK[0..7]
bus sheet U_LCD/LCD_B[0..7] = sheet U_MCU/LCD_B[0..7]
bus sheet U_LCD/LCD_G[0..7] = sheet U_MCU/LCD_G[0..7]
bus sheet U_LCD/LCD_R[0..7] = sheet U_MCU/LCD_R[0..7]
bus sheet U_MCU/A[0..23] = sheet U_Memory/A[0..23]
bus sheet U_MCU/D[0..31] = sheet U_Memory/D[0..31]
bus sheet U_MCU/OCSPI1_IO[0..7] = sheet U_OCSPI/OCSPI1_IO[0..7]
bus sheet U_MCU/ULPI_D[0..7] = sheet U_USB_OTG_HS_externalPHY/ULPI_D[0..7]
harness sheet U_DFSDM_Audio&Motor/M_DFSDM = sheet U_MCU/M_DFSDM
harness sheet U_JTAG&Trace/TRACE = sheet U_MCU/TRACE
harness sheet U_MCU/JOYSTICK = sheet U_MotorControl/JOYSTICK
harness sheet U_MCU/MOTOR = sheet U_MotorControl/MOTOR
harness sheet U_MCU/OCSPI2 = sheet U_OCSPI/OCSPI2

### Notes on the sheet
- Board's Feet
- (near TPG1) GND Test Points
- (AUDIO_NRST)
- (FDCAN_STBY)
- (OPTIONAL)
- (CAMERA_PLUG_IN)
- (CAMERA_RSTI)
- (EXT_RESET)
- (CAMERA_XSDN)
- (near SB30) (OPTIONAL) : need solder bridge configuration to select an optional feature
- (near HW11) PCB
- (near HW21) Stickers
- (MOTOR_GPIO1)
- (MOTOR_GPIO2)
- (WIFI_BOOT)
- (LED2)
- (LED3)
- (LED4)
- (WIFI_RST)
- (WIFI_GPIO)
- (near SB34) (WIFI_DATRDY)
- (WIFI_WKUP)
- to avoid layout stub
- (near SB29) (USB_OTG_FS_PWR_EN)
- (USB_HS_PHY_RESET)
- (USB_OTG_HS_PWR_EN)
- (OPTIONAL) : need solder bridge configuration to select an optional feature
- default VBUS enable = CPEN from USB3320C-EZK
- default USB3320 reset = pull-up on VDIO
- USB HS ext enable & reset (OPTIONAL): MFX

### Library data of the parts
H7-H10 = MCD-00035: POSITION HOLE C6D3R5; Part_Type: Misc; Part_Preference: Recommended; Component_Country_Of_Origin: Unknown; ID: 2482; ShowFields: YES
HW6-HW8 HW24 HW25 = MCD-01240: Rubber Foot (diameter = 10mm, height = 8mm); Part_Type: Mechanical; Manufacturer: 3M; Part_Preference: Recommended; Value: SJ61A4; Provided_By: SUBCO; Component_Country_Of_Origin: Unknown; ID: 3256; ShowFields: YES
HW11 = MCD-00216: PCB, xxxx for PCB number, Y for PCB revision; Part_Type: Misc; Part_Preference: Forbidden; Provided_By: SUBCO; Component_Country_Of_Origin: Unknown; ID: 2653; ShowFields: YES
HW21 = MCD-00547: Sticker to mention board CPN code; Part_Type: Misc; Part_Preference: Recommended; Provided_By: SUBCO; Component_Country_Of_Origin: Unknown; ID: 3197; ShowFields: YES
HW23 = MCD-00235: Sticker to mention board reference + serial number; Part_Type: Misc; Part_Preference: Recommended; Provided_By: SUBCO; Component_Country_Of_Origin: Unknown; ID: 2632; ShowFields: YES
SB29-SB34 = MCD-00071: Solder Bridge ON; Part_Type: Resistor; Manufacturer_Part_Number: RC0603JR-070RL; Manufacturer: YAGEO; Manufacturer_HQ_COO: Unknown; Part_Preference: Recommended; Provided_By: SUBCO; Component_Country_Of_Origin: China; ID: 2521; Order_Code_RS: 199-5647; ShowFields: YES
TPG1-TPG4 = MCD-00713: Vero Technologies 1.02mm Black Terminal Post; Part_Type: Misc; Part_Preference: Recommended; Order_Code_RS: 101-2391; Provided_By: SUBCO; Component_Country_Of_Origin: UK; ID: 3032; ShowFields: YES

## Sheet SDcard.SchDoc: SD Card
size A4; Date: Not used; ApprovedBy: Not used; CheckedBy: Not used; Author: Not used; CompanyName: STMicroelectronics; DrawnBy: Not used; Engineer: Not used; Organization: Not used; Address1: Not used; Address2: Not used; Address3: Not used; Address4: Not used; DocumentNumber: Not used; Revision: Not used; SheetNumber: 9; SheetTotal: 23
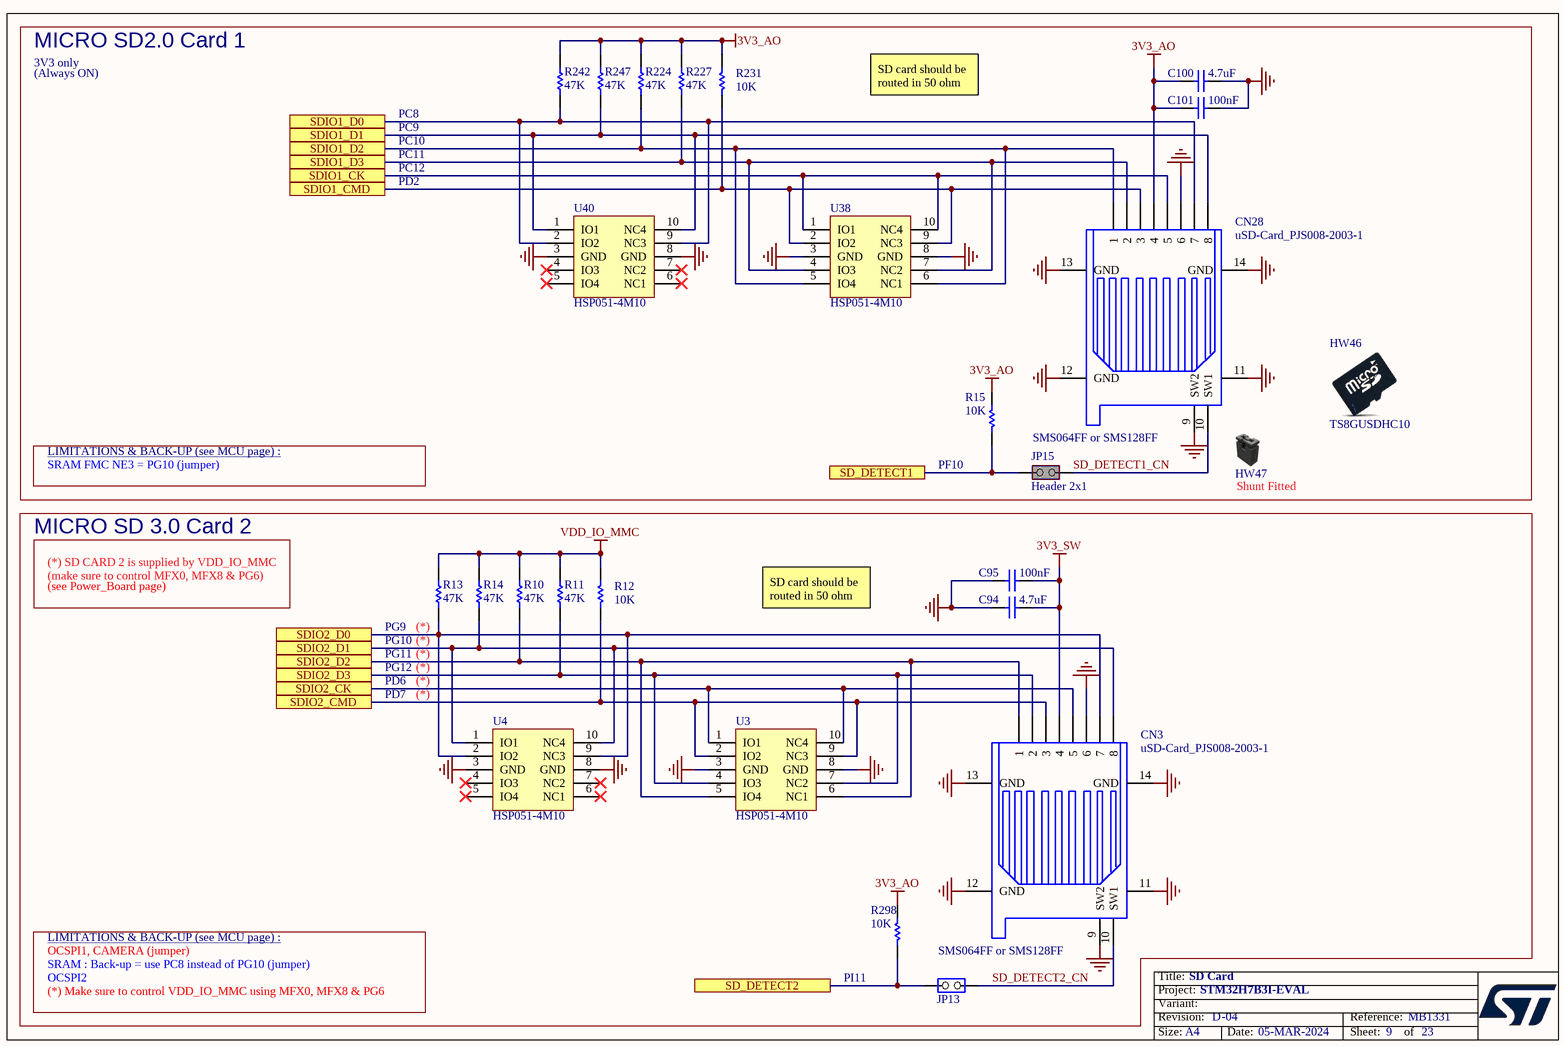
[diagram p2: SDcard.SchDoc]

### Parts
C94  value 4.7uF  [C0805]  (hidden comment: Capacitor)
C95  value 100nF  [C0402]  (hidden comment: Capacitor)
C100  value 4.7uF  [C0805]  (hidden comment: Capacitor)
C101  value 100nF  [C0402]  (hidden comment: Capacitor)
CN3  value uSD-Card_PJS008-2003-1  [CON_MICROSD_YAMAICHI_PJS008-2003-1]  (hidden comment: microSD-PJS008-2003)
CN28  value uSD-Card_PJS008-2003-1  [CON_MICROSD_YAMAICHI_PJS008-2003-1]  (hidden comment: microSD-PJS008-2003)
HW46  value TS8GUSDHC10  (hidden comment: Micro_SD_card)  (no BOM)
HW47  Shunt Black 2.54mm  (value not drawn)  (mechanical)
JP13  Jumper_Header 2x1  [CON_SAMTEC_TSW-102-07-G-S]  (value not drawn)
JP15  value Header 2x1  [CON_SAMTEC_TSW-102-07-G-S]  (hidden comment: Jumper_Header 2x1 Fitted)
R10  value 47K  [R0402]  (hidden comment: Resistor)
R11  value 47K  [R0402]  (hidden comment: Resistor)
R12  value 10K  [R0402]  (hidden comment: Resistor)
R13  value 47K  [R0402]  (hidden comment: Resistor)
R14  value 47K  [R0402]  (hidden comment: Resistor)
R15  value 10K  [R0402]  (hidden comment: Resistor)
R224  value 47K  [R0402]  (hidden comment: Resistor)
R227  value 47K  [R0402]  (hidden comment: Resistor)
R231  value 10K  [R0402]  (hidden comment: Resistor)
R242  value 47K  [R0402]  (hidden comment: Resistor)
R247  value 47K  [R0402]  (hidden comment: Resistor)
R298  value 10K  [R0402]  (hidden comment: Resistor)
U3  HSP051-4M10  [ESD_UQFN-10L_2P5X1_P050]
U4  HSP051-4M10  [ESD_UQFN-10L_2P5X1_P050]
U38  HSP051-4M10  [ESD_UQFN-10L_2P5X1_P050]
U40  HSP051-4M10  [ESD_UQFN-10L_2P5X1_P050]

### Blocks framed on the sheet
MICRO SD2.0 Card 1: C100 C101 CN28 HW46 HW47 JP15 R15 R224 R227 R231 R242 R247 U38 U40
MICRO SD 3.0 Card 2: C94 C95 CN3 JP13 R10-R14 R298 U3 U4

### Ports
SD_DETECT1, SD_DETECT2, SDIO1_CK, SDIO1_CMD, SDIO1_D0, SDIO1_D1, SDIO1_D2, SDIO1_D3, SDIO2_CK, SDIO2_CMD, SDIO2_D0, SDIO2_D1, SDIO2_D2, SDIO2_D3

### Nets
3V3_AO: C100.1 C101.1 CN28.4 R15.2 R224.2 R227.2 R231.2 R242.2 R247.2 R298.2
3V3_SW: C94.2 C95.2 CN3.4
GND: C94.1 C95.1 C100.2 C101.2 CN3.6 CN3.9(SW2) CN3.11(GND) CN3.12(GND) CN3.13(GND) CN3.14(GND) CN28.6 CN28.9(SW2) CN28.11(GND) CN28.12(GND) CN28.13(GND) CN28.14(GND) U3.3(GND) U3.8(GND) U4.3(GND) U4.8(GND) U38.3(GND) U38.8(GND) U40.3(GND) U40.8(GND)
VDD_IO_MMC: R10.2 R11.2 R12.2 R13.2 R14.2
PF10: JP15.1(COMMON) R15.1 ; port SD_DETECT1
SD_DETECT1_CN: CN28.10(SW1) JP15.2(NO)
SD_DETECT2: JP13.2(NO) R298.1 ; port SD_DETECT2
SD_DETECT2_CN: CN3.10(SW1) JP13.1(COMMON)
SDIO1_CK: CN28.5 U38.1(IO1) U38.10(NC4) ; port SDIO1_CK
SDIO1_CMD: CN28.3 R231.1 U38.2(IO2) U38.9(NC3) ; port SDIO1_CMD
SDIO1_D0: CN28.7 R242.1 U40.2(IO2) U40.9(NC3) ; port SDIO1_D0
SDIO1_D1: CN28.8 R247.1 U40.1(IO1) U40.10(NC4) ; port SDIO1_D1
SDIO1_D2: CN28.1 R224.1 U38.5(IO4) U38.6(NC1) ; port SDIO1_D2
SDIO1_D3: CN28.2 R227.1 U38.4(IO3) U38.7(NC2) ; port SDIO1_D3
SDIO2_CK: CN3.5 U3.1(IO1) U3.10(NC4) ; port SDIO2_CK
SDIO2_CMD: CN3.3 R12.1 U3.2(IO2) U3.9(NC3) ; port SDIO2_CMD
SDIO2_D0: CN3.7 R13.1 U4.2(IO2) U4.9(NC3) ; port SDIO2_D0
SDIO2_D1: CN3.8 R14.1 U4.1(IO1) U4.10(NC4) ; port SDIO2_D1
SDIO2_D2: CN3.1 R10.1 U3.5(IO4) U3.6(NC1) ; port SDIO2_D2
SDIO2_D3: CN3.2 R11.1 U3.4(IO3) U3.7(NC2) ; port SDIO2_D3

Not connected (* = marked no-connect by the designer): U4 4(IO3)* 5(IO4)* 6(NC1)* 7(NC2)*; U40 4(IO3)* 5(IO4)* 6(NC1)* 7(NC2)*

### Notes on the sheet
- 3V3 only
- (Always ON)
- PC8
- SD card should be routed in 50 ohm
- PC9
- PC10
- PC11
- PD2
- PC12
- LIMITATIONS & BACK-UP (see MCU page) :
- SMS064FF or SMS128FF
- SRAM FMC NE3 = PG10 (jumper)
- (near R15) PF10
- (near HW47) Shunt Fitted
- (see Power_Board page)
- (*) SD CARD 2 is supplied by VDD_IO_MMC
  (make sure to control MFX0, MFX8 & PG6)
- (near R13) PG9
- (near R13) PG10
- (near R13) PG11
- (near R13) (*)
- (*)
- PG12
- PD6
- PD7
- SRAM : Back-up = use PC8 instead of PG10 (jumper)
- OCSPI1, CAMERA (jumper)
- OCSPI2
- (*) Make sure to control VDD_IO_MMC using MFX0, MFX8 & PG6
- (near R298) PI11

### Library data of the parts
C94 C100 = MCD-04042: Capacitor, MLCC, 4.7uF, 16V, X7R, 10%, 0805, T=1.25mm; Manufacturer_Part_Number: 885012207053; Manufacturer: WURTH ELEKTRONIK; Part_Preference: Recommended; Order_Code_RS: 181-3521P; Component_Country_Of_Origin: Taiwan; ShowFields: YES; ID: 6158
C95 C101 = MCD-00006: Capacitor, MLCC, 100nF, 16V, X7R, 10%, 0402, T=0.5mm; Manufacturer_Part_Number: CC0402KRX7R7BB104; Manufacturer: YAGEO; Alternate_Manufacturer_Part_Number: GCM155R71C104KA55D; Alternate_Manufacturer: MURATA; Part_Preference: Recommended; Partial_Alternate_Internal_Part_Number: MCD-03299; Provided_By: SUBCO; ECCN_US: EAR99; ECCN_EU: NEC; Component_Country_Of_Origin: China; ID: 2474; Order_Code_RS: 9402047; ShowFields: YES
CN3 CN28 = MCD-00023: MicroSD Card Conn, Reversed-Type, Mnt Push-Push, Positionning holes; Part_Type: Connector; Manufacturer_Part_Number: PJS008-2003-1; Manufacturer: YAMAICHI; Part_Preference: Recommended; Provided_By: SUBCO; Component_Country_Of_Origin: Unknown; ID: 2492; ShowFields: YES
HW46 = MCD-00673: 8GB microSDHC SD card Class 10; Part_Type: Accessory; Manufacturer: TRANSCEND; Alternate_Manufacturer_Part_Number: SFSD8192N3BM1TO-I-GE-2B1-STD; Alternate_Manufacturer: SWISSBIT; Part_Preference: Recommended; Provided_By: SUBCO; Component_Country_Of_Origin: Taiwan; ID: 3072; Order_Code_RS: 758-2607; ShowFields: YES
HW47 = MCD-00043: SHUNT 2.54mm BLACK; Part_Type: Misc; Manufacturer: SAMTEC; Alternate_Manufacturer_Part_Number: 316102S111A; Alternate_Manufacturer: JIUBABA; Full_Alternate_Internal_Part_Number: MCD-02388; Manufacturer_HQ_COO: Unknown; Part_Preference: Recommended; Partial_Alternate_Internal_Part_Number: MCD-01849; Value: SNT-100-BK-G; Provided_By: SUBCO; Alternate_EMS: A; Component_Country_Of_Origin: China, Costa Rica, Malaysia, USA, Vietnam; ID: 2551; Order_Code_RS: 158-7784; ShowFields: YES
JP13 = MCD-00045: Header, 2x1, 2,54mm, VR, TH, Height 5.84mm/2.54mm; Manufacturer_Part_Number: TSW-102-07-G-S; Manufacturer: SAMTEC; Part_Type: Connector; Alternate_Manufacturer_Part_Number: 313102S111116;313102S111116; Alternate_Manufacturer: JIUBABA; LIANYI; Full_Alternate_Internal_Part_Number: MCD-02390; Part_Preference: Recommended; Partial_Alternate_Internal_Part_Number: MCD-02957, MCD-03720; Provided_By: SUBCO; Component_Country_Of_Origin: China, Costa Rica, Malaysia, USA, Vietnam; ID: 2545; Order_Code_RS: 2505044; ShowFields: YES
JP15 = MCD-00683: Header, 2x1, 2,54mm, VR, TH, Height 5.84mm/2.54mm - Shunt Fitted by default; Part_Type: Connector; Manufacturer_Part_Number: TSW-102-07-G-S; Manufacturer: SAMTEC; Alternate_Manufacturer_Part_Number: 313102S111116; Alternate_Manufacturer: LIANYI; Full_Alternate_Internal_Part_Number: MCD-02389; Part_Preference: Recommended; Partial_Alternate_Internal_Part_Number: MCD-02957, MCD-03720; Provided_By: SUBCO; Component_Country_Of_Origin: China, Costa Rica, Malaysia, USA, Vietnam; ID: 3057; Order_Code_RS: 155-5312; ShowFields: YES
R10 R11 R13 R14 R224 R227 R242 R247 = MCD-00063: Resistor,47K,0402,1%,1/16W; Manufacturer_Part_Number: RC0402FR-0747KL; Manufacturer: YAGEO; Part_Preference: Recommended; Provided_By: SUBCO; ECCN_US: EAR99; ECCN_EU: NEC; Component_Country_Of_Origin: China; ID: 2528; Order_Code_RS: 9239430; ShowFields: YES
R12 R15 R231 R298 = MCD-00053: Resistor,10K,0402,1%,1/16W; Manufacturer_Part_Number: RC0402FR-0710KL; Manufacturer: YAGEO; BMS_Part_Number: 9131590; Part_Preference: Recommended; Provided_By: SUBCO; ECCN_US: EAR99; ECCN_EU: NEC; Component_Country_Of_Origin: China; ID: 2539; Order_Code_RS: 9239359; ShowFields: YES
U3 U4 U38 U40 = MCD-00667: 4-line ESD protection for high speed lines; Manufacturer: STMICROELECTRONICS; Part_Type: Diode; BMS_Part_Number: 9179041; Manufacturer_HQ_COO: EU; Part_Preference: Recommended; Provided_By: SUBCO with ST control; ECCN_US: EAR99; ECCN_EU: NEC; Component_Country_Of_Origin: Philippines; ID: 3081; ShowFields: YES

## Sheet Camera.SchDoc: Camera
size A4; Date: Not used; ApprovedBy: Not used; CheckedBy: Not used; Author: Not used; CompanyName: STMicroelectronics; DrawnBy: Not used; Engineer: Not used; Organization: Not used; Address1: Not used; Address2: Not used; Address3: Not used; Address4: Not used; DocumentNumber: Not used; Revision: Not used; SheetNumber: 12; SheetTotal: 23
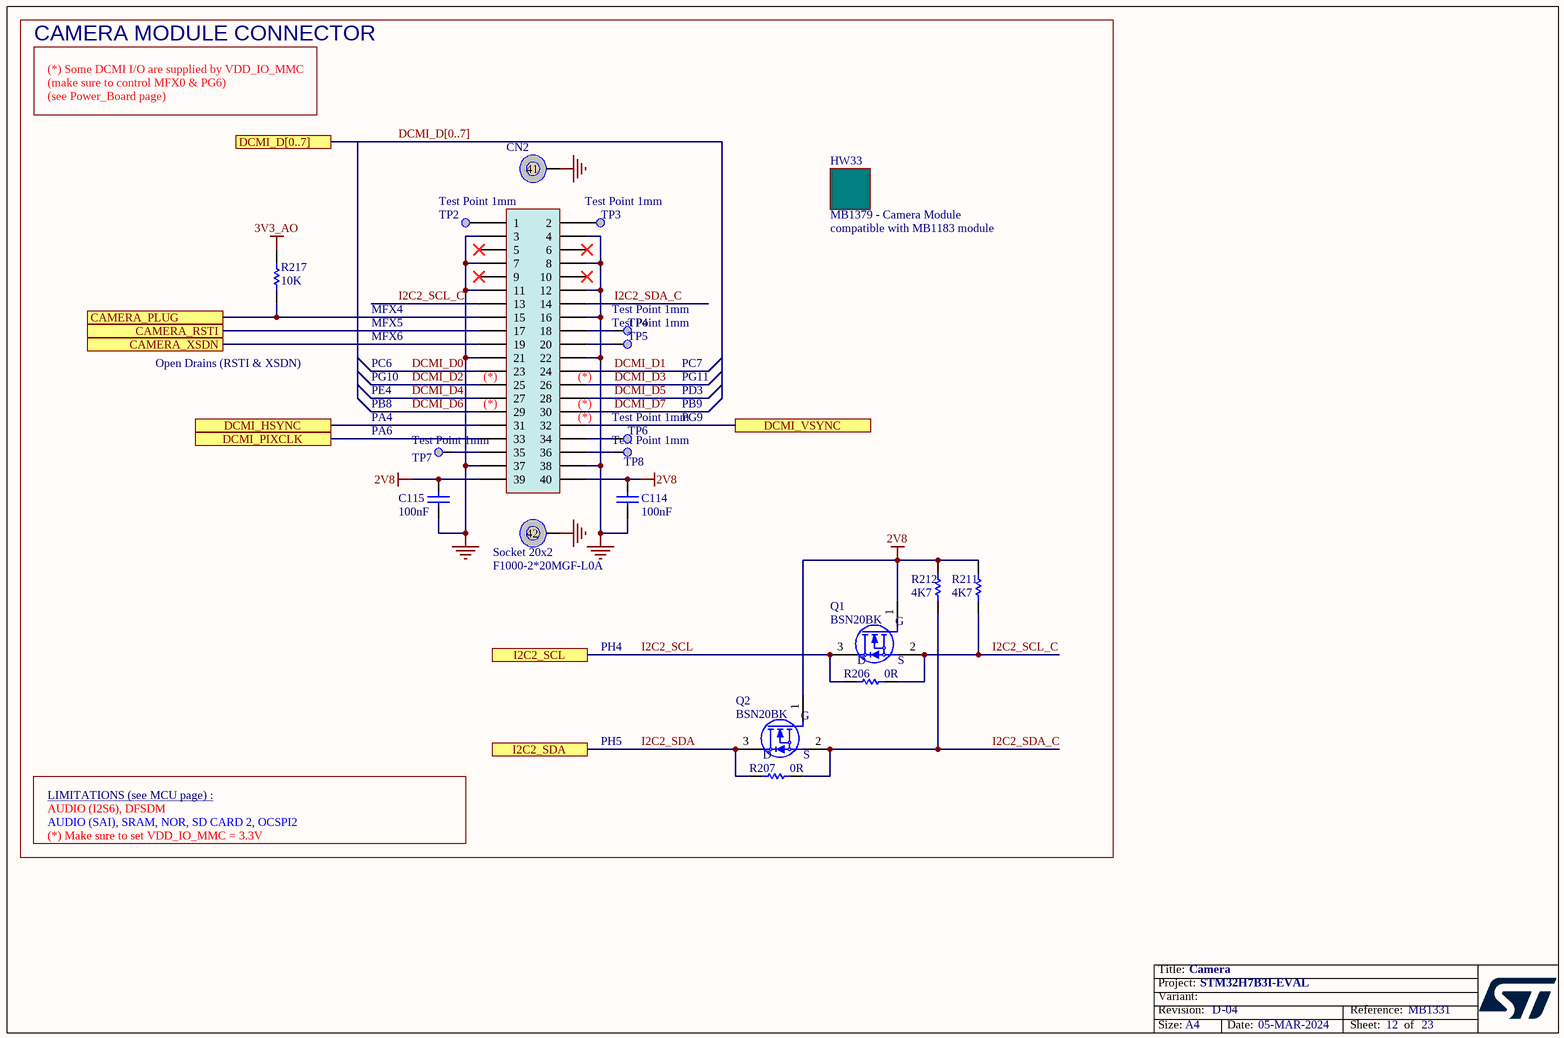
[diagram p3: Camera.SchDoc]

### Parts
C114  value 100nF  [C0402]  (hidden comment: Capacitor)
C115  value 100nF  [C0402]  (hidden comment: Capacitor)
CN2  value Socket 20x2  [CON_SAMTEC_CLM-120-02-L-D_Reverse-to-Camera]  (hidden comment: Socket 20x2 CLM_Reverse_for_camera)
HW33  value MB1379 - Camera Module  [MOD_CAMERA_MB1379]  (hidden comment: Daughter_Board)
Q1  value BSN20BK  [MOS_SOT23]  (hidden comment: BSN20)
Q2  value BSN20BK  [MOS_SOT23]  (hidden comment: BSN20)
R206  value 0R  [R0603]  (hidden comment: Resistor)
R207  value 0R  [R0603]  (hidden comment: Resistor)
R211  value 4K7  [R0402]  (hidden comment: Resistor)
R212  value 4K7  [R0402]  (hidden comment: Resistor)
R217  value 10K  [R0402]  (hidden comment: Resistor)
TP2  value Test Point 1mm  [TP_SMD_1MM]  (hidden comment: Test Point)  (no BOM)
TP3  value Test Point 1mm  [TP_SMD_1MM]  (hidden comment: Test Point)  (no BOM)
TP4  value Test Point 1mm  [TP_SMD_1MM]  (hidden comment: Test Point)  (no BOM)
TP5  value Test Point 1mm  [TP_SMD_1MM]  (hidden comment: Test Point)  (no BOM)
TP6  value Test Point 1mm  [TP_SMD_1MM]  (hidden comment: Test Point)  (no BOM)
TP7  value Test Point 1mm  [TP_SMD_1MM]  (hidden comment: Test Point)  (no BOM)
TP8  value Test Point 1mm  [TP_SMD_1MM]  (hidden comment: Test Point)  (no BOM)

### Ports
CAMERA_PLUG, CAMERA_RSTI, CAMERA_XSDN, DCMI_D[0..7], DCMI_HSYNC, DCMI_PIXCLK, DCMI_VSYNC, I2C2_SCL, I2C2_SDA

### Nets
2V8: C114.2 C115.2 CN2.39 CN2.40 Q1.1(G) Q2.1(G) R211.2 R212.2
3V3_AO: R217.2
GND: C114.1 C115.1 CN2.3 CN2.4 CN2.7 CN2.8 CN2.11 CN2.12 CN2.16 CN2.21 CN2.22 CN2.37 CN2.38 CN2.41 CN2.42
CAMERA_PLUG: CN2.15 R217.1 ; port CAMERA_PLUG
CAMERA_RSTI: CN2.17 ; port CAMERA_RSTI
CAMERA_XSDN: CN2.19 ; port CAMERA_XSDN
DCMI_D0: CN2.23
DCMI_D1: CN2.24
DCMI_D2: CN2.25
DCMI_D3: CN2.26
DCMI_D4: CN2.27
DCMI_D5: CN2.28
DCMI_D6: CN2.29
DCMI_D7: CN2.30
DCMI_HSYNC: CN2.31 ; port DCMI_HSYNC
DCMI_PIXCLK: CN2.33 ; port DCMI_PIXCLK
DCMI_VSYNC: CN2.32 ; port DCMI_VSYNC
I2C2_SCL: Q1.3(D) R206.1 ; port I2C2_SCL
I2C2_SCL_C: CN2.13 Q1.2(S) R206.2 R211.1
I2C2_SDA: Q2.3(D) R207.1 ; port I2C2_SDA
I2C2_SDA_C: CN2.14 Q2.2(S) R207.2 R212.1
NetCN2_1: CN2.1 TP2.1
NetCN2_2: CN2.2 TP3.1
NetCN2_18: CN2.18 TP4.1
NetCN2_20: CN2.20 TP5.1
NetCN2_34: CN2.34 TP6.1
NetCN2_35: CN2.35 TP7.1
NetCN2_36: CN2.36 TP8.1

Not connected (* = marked no-connect by the designer): CN2 5* 6* 9* 10*

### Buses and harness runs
bus DCMI_D[0..7] = port DCMI_D[0..7]

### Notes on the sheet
- CAMERA MODULE CONNECTOR
- (*) Some DCMI I/O are supplied by VDD_IO_MMC
  (make sure to control MFX0 & PG6)
  (see Power_Board page)
- compatible with MB1183 module
- MFX4
- Open Drains (RSTI & XSDN)
- PC6
- PG10
- MFX5
- MFX6
- (near CN2) (*)
- PC7
- PG11
- PE4
- PB8
- PA4
- PA6
- PB9
- PG9
- PD3
- (near CN2) F1000-2*20MGF-L0A
- PH4
- PH5
- LIMITATIONS (see MCU page) :
- AUDIO (SAI), SRAM, NOR, SD CARD 2, OCSPI2
- AUDIO (I2S6), DFSDM
- (*) Make sure to set VDD_IO_MMC = 3.3V

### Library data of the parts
C114 C115 = MCD-00006: as C95 on sheet SDcard
CN2 = MCD-00138: Socket, 20x2, 1.0mm, VR, SMT, Height 2.26mm. Symbol & Footprint dedicated to MB1183 & MB1379 camera modules (not in line with Samtec datasheet); Part_Type: Connector; Manufacturer_Part_Number: CLM-120-02-L-D; Part_Preference: Recommended; Provided_By: SUBCO; ECCN_US: EAR99; ECCN_EU: NEC; Component_Country_Of_Origin: China, Costa Rica, Malaysia, USA, Vietnam; ID: 2727; Order_Code_RS: 766-8748; ShowFields: YES
HW33 = MCD-01034: Camera Module(to replace MB1183 module); Part_Type: Misc; Manufacturer: STMICROELECTRONICS; BMS_Part_Number: MB1379; Part_Preference: Recommended; Provided_By: SUBCO with ST control; Component_Country_Of_Origin: Unknown; ID: 2985; ShowFields: YES
Q1 Q2 = MCD-01969: N-channel enhancement mode field-effect transistor; Manufacturer: Nexperia; Part_Preference: Recommended; ECCN_US: EAR99; ECCN_EU: NEC; Provided_By: SUBCO; Component_Country_Of_Origin: China; ID: 4069; Order_Code_RS: 136-4845; ShowFields: YES
R206 R207 = MCD-00056: Resistor,0R,0603,5%,1/10W; Manufacturer_Part_Number: RC0603JR-070RL; Manufacturer: YAGEO; Part_Preference: Recommended; Provided_By: SUBCO; ECCN_US: EAR99; ECCN_EU: NEC; Component_Country_Of_Origin: China; ID: 2536; Order_Code_RS: 9233130RL; ShowFields: YES
R211 R212 = MCD-00065: Resistor,4K7,0402,1%,1/16W; Manufacturer_Part_Number: RC0402FR-074K7L; Manufacturer: YAGEO; Alternate_Manufacturer_Part_Number: RT0402FRE074K7L; Part_Preference: Recommended; Partial_Alternate_Internal_Part_Number: MCD-03300; Provided_By: SUBCO; ECCN_US: EAR99; ECCN_EU: NEC; Component_Country_Of_Origin: China; ID: 2526; Order_Code_RS: 9239316; ShowFields: YES
R217 = MCD-00053: as R12 on sheet SDcard
TP2-TP8 = MCD-00074: Test Point 1mm; Part_Type: Misc; Part_Preference: Recommended; Component_Country_Of_Origin: Unknown; ID: 2518; ShowFields: YES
